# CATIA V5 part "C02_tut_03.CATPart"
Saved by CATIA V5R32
Part number: C02tut3
Bounding box of the stored display mesh (mm): x 0 to 40, y -40 to 40, z -30 to 30
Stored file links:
  D:\PROJECTS\Project 2022\CATIA V5 6R 2022\Resources\Tutorial Files\c02_catia_v5_6r2021_tut\C02_tut_03.CATPart
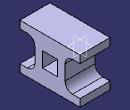
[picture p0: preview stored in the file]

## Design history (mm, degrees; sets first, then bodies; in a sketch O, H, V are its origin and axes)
Body1 (main body)
  Sketch1 on yz-plane, origin (0, 0, 0), H (0, 1, 0), V (0, 0, 1)
    line L1 (-40, -30) -> (40, -30)
    line L2 (40, -30) -> (40, -20)
    line L3 (40, -20) -> (30, -20)
    arc A1 centre (30, -10) radius 10 from (30, -20) to (20, -10) cw
    line L4 (20, -10) -> (20, 10)
    arc A2 centre (30, 10) radius 10 from (20, 10) to (30, 20) cw
    line L5 (30, 20) -> (40, 20)
    point P10 (40, 20)
    line L6 (40, 20) -> (40, 30)
    line L7 (40, 30) -> (-40, 30)
    line L8 (-40, 30) -> (-40, 20)
    point P13 (-40, 20)
    line L9 (-40, 20) -> (-30, 20)
    arc A3 centre (-30, 10) radius 10 from (-30, 20) to (-20, 10) cw
    line L10 (-20, 10) -> (-20, -10)
    arc A4 centre (-30, -10) radius 10 from (-20, -10) to (-30, -20) cw
    line L11 (-30, -20) -> (-40, -20)
    point P20 (-40, -20)
    line L12 (-40, -20) -> (-40, -30)
    line L13 (10, 10) -> (10, -10)
    line L14 (10, -10) -> (-10, -10)
    line L15 (-10, -10) -> (-10, 10)
    line L16 (-10, 10) -> (10, 10)
    distance L13 L15 = 20
    distance L14 L16 = 20
    horizontal: L1 H, L3 H, L7 H, L14 H, L16 H
    vertical: L2 V, L6 V, L8 V, L12 V, L13 V, L15 V
    tangency: A1 L3, L4 A1, A2 L2, A2 L4, L5 A2, L9 A2, A3 L8, A3 L9, L10 A3, A4 L3, A4 L10, L11 A4
    coincidence: P10 L2, P13 L5, P20 L8
    equidistance: L13 L15 O, L14 L16 O
  Pad1: profile Sketch1, direction (1, 0, 0), length 40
